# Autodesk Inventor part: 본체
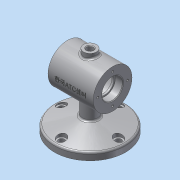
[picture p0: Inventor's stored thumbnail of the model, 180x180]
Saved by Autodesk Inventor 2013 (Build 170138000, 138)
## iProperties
Created: 2018-12
Part Number: 본체
Material: 알루미늄 6061
Document SubType Name: Modeling
Designer: dgall
Density: 1 g/cm^3
Author: dgall
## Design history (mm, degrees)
sketch "스케치1"
  geometry: L1 (0, 0)-(70, 0); L2 (70, 0)-(70, 30); L3 (70, 30)-(0, 30); L4 (0, 30)-(0, 0)
  constraints: 8 end point, 2 parallel, 1 horizontal, 1 perpendicular
  dimensions: "d0" = 70 distance of L2.end L3.end; "d2" = 60 diameter of L3 L1
revolve "회전1" sketch "스케치1" stored, may be unused: angle "d3" = 90 deg
node "작업 평면1"
sketch "스케치2"
  geometry: L1 (70, -30)-(70, 30) reference; L2 (0, -30)-(0, 30) reference; L3 (0, 30)-(70, 30) reference; C1 r 55 at (35, 0); 3 further points
  constraints: 2 midpoint, 1 centre point, 1 horizontal alignment, 1 vertical alignment
  dimensions: "d5" = 110 diameter of C1
extrude "돌출1" join sketch "스케치2" distance "d7" = 11; taper "d8" = 0 deg
sketch "스케치5"
  geometry: C1 r 55 at (0, 0) reference; C2 r 55 at (0, 0); 1 further point
  constraints: 1 centre point, 1 coincident, 1 concentric
extrude "돌출2" join sketch "스케치5" distance "d11" = 20; taper "d12" = -75 deg
node "작업 평면2"
sketch "스케치6"
  geometry: C1 r 55 at (0, 0) reference; C2 r 12 at (0, 0); 1 further point
  constraints: 1 centre point, 1 coincident
  dimensions: "d14" = 24 diameter of C2
extrude "돌출3" join sketch "스케치6" stored distance "d16" = 20; taper "d17" = 0 deg
extrude "돌출4" join sketch "스케치6" stored distance "d18" = 20; taper "d19" = 0 deg
node "작업 평면3"
sketch "스케치7"
  geometry: L1 (-35, 30)-(35, 30) reference; C1 r 10 at (0, 0); 1 further point
  constraints: 1 centre point, 1 horizontal alignment
  dimensions: "d21" = 20 diameter of C1; "d23" = 35 distance of C1.centre point (-35, 0)
extrude "돌출5" join sketch "스케치7" stored distance "d24" = 20; taper "d25" = 0 deg
sketch "스케치8"
  geometry: L1 (0, 16)-(-12, 16); L2 (-12, 16)-(-12, 14); L3 (-12, 14)-(-15, 14); L4 (-15, 14)-(-15, 25); L5 (-15, 25)-(-55, 25); L6 (-55, 25)-(-55, 14); L7 (-55, 14)-(-58, 14); L8 (-58, 14)-(-58, 16); L9 (-58, 16)-(-70, 16); L10 (-70, 30)-(-70, -30) reference; L11 (0, 16)-(0, 0); L12 (0, 0)-(-70, 0); L13 (-70, 16)-(-70, 0)
  constraints: 24 end point, 7 parallel, 4 equal length, 2 collinear, 1 horizontal, 1 midpoint, 1 perpendicular, 1 point on line
  dimensions: "d26" = 32 diameter of L1 L12; "d28" = 28 diameter of L3 L12; "d29" = 50 diameter of L5 L12; "d30" = 40 distance of L4.end L5.end; "d31" = 12 distance of L1.start L1.end
revolve "회전3" sketch "스케치8" stored, may be unused: angle "d32" = 90 deg
sketch "스케치9"
  geometry: C1 r 10 at (0, 0) reference; C2 r 5 at (0, 0); 1 further point
  constraints: 1 centre point, 1 coincident
  dimensions: "d33" = 10 diameter of C2
extrude "돌출6" cut sketch "스케치9" stored distance "d35" = 20; taper "d36" = 0 deg
sketch "스케치10"
  geometry: C1 r 16 at (0, 0) reference; 1 further point
  constraints: 1 horizontal alignment
  dimensions: "d37" = 23 distance of C1.centre point (-23, 0)
hole "구멍1" sketch "스케치10" at (-23, 0) diameter "d38" = 3.242; stored, may be unused: countersink angle "d42" = 90 deg, drill point angle "d44" = 118 deg; dims "d39" = 8, "d40" = 4, "d41" = 2, "d43" = 10
node "작업 평면4"
sketch "스케치11" dims "d48" = 88
  geometry: C1 r 55 at (0, 0) reference; C2 r 4.5 at (0, 44); 2 further points
  constraints: 2 vertical alignment, 1 centre point, 1 coincident, 2 other
  dimensions: "d50" = 9 diameter of C2
extrude "돌출7" cut sketch "스케치11" distance "d51" = 10; taper "d52" = 0 deg
sketch "스케치12"
  geometry: C1 r 4.5 at (0, 0) reference; C2 r 7 at (0, 0); 1 further point
  constraints: 1 centre point, 1 coincident
  dimensions: "d53" = 14 diameter of C2
extrude "돌출8" cut sketch "스케치12" stored distance "d55" = 10; taper "d56" = 0 deg
fillet "모깎기1" dims "d60" = 0.3
fillet "모깎기2" dims "d61" = 3
chamfer "모따기1" distance "d62" = 1; stored, may be unused: second distance "d63" = 2, angle "d64" = 45 deg
fillet "모깎기3" dims "d65" = 3
node "작업 평면5"
sketch "스케치13"
  geometry: L1 (0, -30)-(0, 30) reference; 2 further points
  constraints: 1 other
  dimensions: "d67" = 35 distance from line of point (35, 0) L1; "d68" = 30 vertical distance of L1.end point (35, 0)
feature "엠보싱1" sketch "스케치13" dims "d0" = 70, "d2" = 60, "d12" = -75 deg, "d69" = 0.5, "d70" = 0
node "솔리드1"
pattern_circular "원형 패턴1" dims angle "d46" = 360 deg
mirror "대칭1"
pattern_circular "원형 패턴2" dims angle "d58" = 360 deg
node "투영된 루프1"
other parameters: "d4" = -75, "d13" = -32, "d20" = -112, "d66" = -44.75
